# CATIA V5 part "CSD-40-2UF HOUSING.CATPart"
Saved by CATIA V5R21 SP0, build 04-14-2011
Part number: CSD-40-2UF HOUSING
Revision: ANY
Definition: UNKNOWN
Nomenclature: CSD-40-2UF HOUSING
Source: Unknown
Bounding box of the stored display mesh (mm): x 0 to 45, y -85 to 84.802, z -85 to 85
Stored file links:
  C:\Users\MIRCEA\Desktop\PRRO\CATIAV5\CSD-40-2UF HOUSING.CATPart
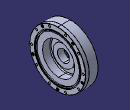
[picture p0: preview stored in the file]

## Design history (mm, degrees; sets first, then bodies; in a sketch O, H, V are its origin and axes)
Body1 "CirPattern4" (main body)
  Solid1: solid without history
